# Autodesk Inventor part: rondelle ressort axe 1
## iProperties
Author: Administrateur
Created: 2001-04
Part Number: rondelle ressort axe 1
Material: Par défaut
Document SubType Name: Tôlerie
Designer: Administrateur
Control State: 0
Master: False
Checked Out: False
PropertySet Name: Design Tracking Control
Shininess: 20.0
PropertySet Name: _Private Model Information
Length Units: 11269
Angle Units: 11283
Time Units: 11279
Mass Units: 11290
Length Display Precision: 3
Angle Display Precision: 2
Compacted: False
Density: 0.0
Volumn: 0.0
Area: 0.0
PropertySet Name: Model Information
